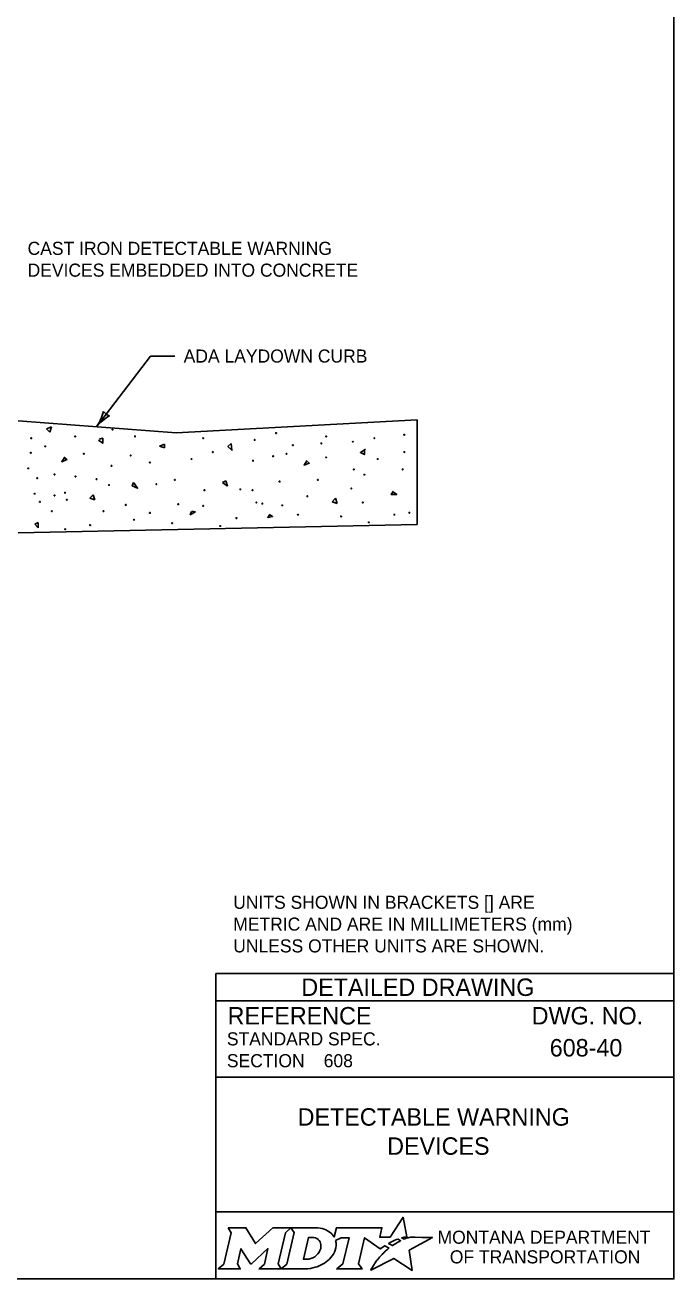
# Model space of a CAD drawing. Extents: x 49991.4 to 50021, y 49987.6 to 50011.4.
# Drawn here: x 50005.64 to 50008.61, y 50000.06 to 50005.81 of the extents above; entities that cross this region are included whole.
import ezdxf

# ---------------------------------------------------------------- set-up
doc = ezdxf.new("R2010")
doc.units = 0
for name, color, linetype in [('Level 1', 7, 'Continuous'), ('Level 2', 7, 'Continuous'), ('Level 3', 7, 'Continuous'), ('Level 5', 7, 'Continuous')]:
    doc.layers.add(name, color=color, linetype=linetype)

msp = doc.modelspace()

# ---------------------------------------------------------------- linework, layer by layer
at = {"layer": 'Level 1'}
for p, q in [((50005.6078, 50003.9963), (50006.3318, 50003.9414)), ((50006.3318, 50003.9414), (50007.4378, 50004.0017)), ((50007.4378, 50003.5221), (50007.4378, 50004.0017)), ((50005.7374, 50003.9607), (50005.7602, 50003.9687)), ((50005.7526, 50003.9448), (50005.7374, 50003.9607)), ((50005.7602, 50003.9687), (50005.7526, 50003.9448)), ((50006.2556, 50003.881), (50006.2785, 50003.889)), ((50006.2785, 50003.8731), (50006.2556, 50003.881)), ((50006.2785, 50003.889), (50006.2785, 50003.8731)), ((50006.5452, 50003.7138), (50006.5605, 50003.7217)), ((50006.5681, 50003.6978), (50006.5452, 50003.7138)), ((50006.5605, 50003.7217), (50006.5681, 50003.6978)), ((50005.9371, 50003.6422), (50005.9524, 50003.6581)), ((50005.9601, 50003.6342), (50005.9371, 50003.6422)), ((50005.9524, 50003.6581), (50005.9601, 50003.6342)), ((50007.0482, 50003.6261), (50007.0635, 50003.6421)), ((50007.0635, 50003.6421), (50007.0711, 50003.6181)), ((50007.0711, 50003.6181), (50007.0482, 50003.6261)), ((50007.4378, 50003.5221), (50005.6078, 50003.4839)), ((50005.684, 50003.5226), (50005.6993, 50003.5305)), ((50005.6993, 50003.5066), (50005.684, 50003.5226)), ((50005.6993, 50003.5305), (50005.6993, 50003.5066))]:
    msp.add_line(p, q, dxfattribs=at)
msp.add_lwpolyline([(50008.6146, 50011.2628), (50000.3356, 50011.2628), (50000.3356, 50000.0624), (50008.6146, 50000.0624)], close=True, dxfattribs=at)
for points in [[(50005.9786, 50003.9121), (50005.9957, 50003.9169), (50005.9957, 50003.8943), (50005.977, 50003.9088)], [(50006.5848, 50003.8927), (50006.5693, 50003.8796), (50006.588, 50003.8618), (50006.5848, 50003.8927)], [(50007.2005, 50003.8666), (50007.1771, 50003.852), (50007.1958, 50003.8422), (50007.1958, 50003.8618)], [(50005.8205, 50003.829), (50005.808, 50003.8095), (50005.8312, 50003.8193), (50005.8173, 50003.8307)], [(50006.9316, 50003.813), (50006.9191, 50003.7935), (50006.9423, 50003.8032), (50006.9284, 50003.8146)], [(50006.1371, 50003.7139), (50006.1309, 50003.6992), (50006.1558, 50003.6878), (50006.1371, 50003.7139)], [(50007.3279, 50003.6733), (50007.3186, 50003.6587), (50007.3434, 50003.6587), (50007.3248, 50003.6733)], [(50006.403, 50003.5807), (50006.3967, 50003.566), (50006.4201, 50003.579), (50006.4045, 50003.5823)], [(50006.7621, 50003.5677), (50006.7527, 50003.553), (50006.7746, 50003.5579), (50006.7605, 50003.5677)]]:
    msp.add_lwpolyline(points, dxfattribs=at)
for centre in [(50005.6681, 50003.9169), (50005.8692, 50003.9251), (50006.0406, 50003.9567), (50006.1436, 50003.9251), (50006.4561, 50003.9172), (50006.7906, 50003.9405), (50007.0201, 50003.9251), (50007.2411, 50003.9172), (50007.3783, 50003.9331), (50005.7323, 50003.8799), (50006.6924, 50003.9092), (50006.8676, 50003.8853), (50006.998, 50003.8931), (50007.1425, 50003.9011), (50005.6655, 50003.8505), (50005.909, 50003.8456), (50006.1237, 50003.8378), (50006.2122, 50003.8056), (50006.4027, 50003.8216), (50006.5006, 50003.8534), (50006.6847, 50003.8136), (50006.7766, 50003.8344), (50006.8384, 50003.8454), (50007.0201, 50003.8295), (50007.2564, 50003.8216), (50007.3787, 50003.8534), (50005.6541, 50003.7789), (50005.7744, 50003.751), (50005.8709, 50003.742), (50006.0357, 50003.79), (50007.1468, 50003.7739), (50007.1954, 50003.7499), (50007.3707, 50003.7738), (50005.6956, 50003.734), (50005.9672, 50003.7292), (50006.0244, 50003.7025), (50006.2416, 50003.7064), (50006.3265, 50003.726), (50006.8067, 50003.718), (50006.982, 50003.726), (50007.1354, 50003.6865), (50005.6833, 50003.6627), (50005.7745, 50003.6547), (50005.8228, 50003.6668), (50005.831, 50003.6348), (50006.462, 50003.6785), (50006.6267, 50003.6825), (50006.6825, 50003.6785), (50006.9339, 50003.6508), (50005.7077, 50003.6253), (50005.7625, 50003.5826), (50005.9988, 50003.5826), (50006.1014, 50003.611), (50006.2122, 50003.5746), (50006.3418, 50003.6144), (50006.4561, 50003.6065), (50006.7, 50003.6224), (50006.7276, 50003.6172), (50006.8188, 50003.6093), (50007.1878, 50003.6224), (50007.4015, 50003.5752), (50005.9378, 50003.5188), (50006.1389, 50003.5434), (50006.1389, 50003.5434), (50006.3138, 50003.5276), (50006.5345, 50003.5145), (50006.6085, 50003.5507), (50006.8905, 50003.5666), (50007.0887, 50003.5587), (50007.2153, 50003.5315), (50007.3326, 50003.5666), (50005.8234, 50003.4997)]:
    msp.add_ellipse(centre, major_axis=(0, 0.00194), ratio=0.95672, dxfattribs=at)
at = {"layer": 'Level 2'}
for p, q in [((50008.6146, 50001.4624), (50006.5146, 50001.4624)), ((50006.5146, 50001.4624), (50006.5146, 50000.0624)), ((50008.6146, 50001.3374), (50006.5146, 50001.3374)), ((50008.2507, 50001.1223), (50008.2507, 50001.1223)), ((50007.0089, 50001.0629), (50007.0089, 50001.0629)), ((50008.6146, 50000.9874), (50006.5146, 50000.9874)), ((50007.5646, 50000.7383), (50007.5646, 50000.7383)), ((50008.6146, 50000.3693), (50006.5146, 50000.3693))]:
    msp.add_line(p, q, dxfattribs=at)
for points in [[(50006.5701, 50000.2974), (50006.5842, 50000.274), (50006.5507, 50000.1307), (50006.525, 50000.1082), (50006.6266, 50000.1082), (50006.6131, 50000.131), (50006.6293, 50000.2011), (50006.673, 50000.1321), (50006.6783, 50000.1321), (50006.7534, 50000.2016), (50006.737, 50000.1305), (50006.7123, 50000.1085), (50006.8139, 50000.1085), (50006.8001, 50000.1318), (50006.8333, 50000.2742)], [(50006.8333, 50000.2742), (50006.8586, 50000.2974), (50006.7762, 50000.2974), (50006.6966, 50000.2244), (50006.6521, 50000.2971), (50006.5701, 50000.2974)], [(50006.9722, 50000.2974), (50006.8586, 50000.2974), (50006.8733, 50000.2745), (50006.8394, 50000.1307), (50006.8139, 50000.1085), (50006.9245, 50000.1085)], [(50007.3771, 50000.2447), (50007.3668, 50000.2503), (50007.3784, 50000.2531), (50007.39, 50000.2551), (50007.3726, 50000.3452), (50007.3131, 50000.2539), (50007.2658, 50000.2532), (50007.2761, 50000.2973), (50007.0669, 50000.2974), (50007.0568, 50000.2549), (50007.051, 50000.2632)], [(50006.9962, 50000.2107), (50006.995, 50000.2026), (50006.9918, 50000.1933), (50006.9876, 50000.1851), (50006.982, 50000.1776), (50006.9755, 50000.1707), (50006.9676, 50000.1644), (50006.9593, 50000.1597), (50006.9502, 50000.1558), (50006.9411, 50000.1535), (50006.9319, 50000.1526), (50006.916, 50000.1526), (50006.9396, 50000.2526), (50006.9556, 50000.2526), (50006.9632, 50000.252), (50006.9708, 50000.2501), (50006.9774, 50000.2471), (50006.9835, 50000.2429), (50006.9883, 50000.2379), (50006.992, 50000.2319), (50006.9947, 50000.2257), (50006.9963, 50000.2183), (50006.9963, 50000.2153), (50006.9962, 50000.2107)], [(50007.0636, 50000.2383), (50007.0882, 50000.2514), (50007.1251, 50000.2514), (50007.0965, 50000.1309), (50007.069, 50000.1082), (50007.1852, 50000.1082), (50007.1682, 50000.1311), (50007.1964, 50000.2513), (50007.2677, 50000.1996), (50007.2888, 50000.2147), (50007.3085, 50000.2038)], [(50007.2527, 50000.1479), (50007.2374, 50000.1235), (50007.2327, 50000.116), (50007.2269, 50000.1074), (50007.2246, 50000.1031), (50007.3299, 50000.1562), (50007.4138, 50000.1011), (50007.4007, 50000.1938), (50007.5076, 50000.2522), (50007.4583, 50000.253), (50007.4282, 50000.2534), (50007.4074, 50000.2537), (50007.4006, 50000.2522), (50007.3957, 50000.251), (50007.3873, 50000.2487), (50007.3771, 50000.2447)], [(50007.3267, 50000.2171), (50007.3243, 50000.2154), (50007.306, 50000.225), (50007.3163, 50000.2307), (50007.3204, 50000.2329), (50007.329, 50000.2369), (50007.3347, 50000.2395), (50007.3426, 50000.2425), (50007.3499, 50000.2452), (50007.3617, 50000.2378), (50007.3577, 50000.2357), (50007.3531, 50000.2332), (50007.3489, 50000.231), (50007.3439, 50000.2281), (50007.342, 50000.227), (50007.3393, 50000.2254), (50007.3368, 50000.224), (50007.3345, 50000.2224), (50007.3319, 50000.2206), (50007.3292, 50000.2188), (50007.3267, 50000.2171)], [(50006.9702, 50000.1158), (50006.9786, 50000.1184), (50006.9916, 50000.1238), (50007.012, 50000.1348)], [(50007.2666, 50000.164), (50007.2666, 50000.164)]]:
    msp.add_lwpolyline(points, dxfattribs=at)
for centre, radius, start, end in [((50006.9953, 50000.219), 0.0709, 339.53292, 15.85821), ((50006.9513, 50000.2363), 0.1183, 300.91025, 339.13831)]:
    msp.add_arc(centre, radius, start, end, dxfattribs=at)
for centre, major_axis, ratio, start_param, end_param in [((50006.9701, 50000.25), (0.0834, -0.0037), 0.568097, 0.61298, 1.570796), ((50007.0257, 50000.2573), (0.0361, -0.0295), 0.469099, 1.225588, 1.570796), ((50007.2764, 50000.1742), (-0.0098, -0.0102), 0.016458, 3.141593, 6.279097), ((50007.2974, 50000.1941), (-0.0112, -0.0097), 0.021651, 3.157348, 6.283185), ((50007.2597, 50000.1559), (-0.00694, -0.00806), 0.008222, 0, 3.137361), ((50006.9248, 50000.2568), (0, 0.1484), 0.987302, 3.139398, 3.456847)]:
    msp.add_ellipse(centre, major_axis=major_axis, ratio=ratio, start_param=start_param, end_param=end_param, dxfattribs=at)
at = {"layer": 'Level 3'}
for p, q in [((50005.9668, 50003.9691), (50006.2143, 50004.2938)), ((50006.2143, 50004.2938), (50006.3267, 50004.2938))]:
    msp.add_line(p, q, dxfattribs=at)
for centre, radius, start, end in [((50005.7748, 50004.101), 0.233, 325.52072, 344.77057), ((50006.0445, 50004.071), 0.0548, 214.83223, 250.55459), ((50006.138, 50003.8272), 0.2223, 120.14942, 140.33293)]:
    msp.add_arc(centre, radius, start, end, dxfattribs=at)

# ---------------------------------------------------------------- texts
at = {"layer": 'Level 2'}
for s, height, p in [('CAST IRON DETECTABLE WARNING', 0.06, (50005.6511, 50004.7576)), ('DEVICES EMBEDDED INTO CONCRETE', 0.06, (50005.6511, 50004.6576)), ('ADA LAYDOWN CURB', 0.06, (50006.3667, 50004.2638)), ('UNITS SHOWN IN BRACKETS [] ARE ', 0.06, (50006.5939, 50001.7593)), ('METRIC AND ARE IN MILLIMETERS (mm) ', 0.06, (50006.5939, 50001.6593)), ('UNLESS OTHER UNITS ARE SHOWN.', 0.06, (50006.5939, 50001.5593)), ('REFERENCE', 0.08, (50006.5682, 50001.229)), ('DWG. NO.', 0.08, (50007.9624, 50001.229)), ('STANDARD SPEC.', 0.06, (50006.5649, 50001.133)), ('608-40', 0.08, (50008.0451, 50001.0823)), ('SECTION', 0.06, (50006.5649, 50001.033)), ('608', 0.06, (50007.0089, 50001.0329)), ('DETECTABLE WARNING', 0.08, (50006.8892, 50000.765)), ('DEVICES', 0.08, (50007.2998, 50000.6316)), ('MONTANA DEPARTMENT', 0.06, (50007.5308, 50000.2236)), ('OF TRANSPORTATION', 0.06, (50007.587, 50000.1336))]:
    msp.add_text(s, height=height, dxfattribs=at).set_placement(p)
at = {"layer": 'Level 5'}
msp.add_text('DETAILED DRAWING', height=0.0799, dxfattribs=at).set_placement((50006.9063, 50001.3599))

doc.saveas('drawing.dxf')
